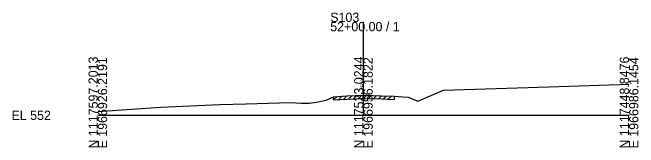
# Model space of a CAD drawing. Extents: x -26 to 163, y -10 to 24018.
# Drawn here: x -25.7 to 162.8, y 1490.3 to 1531 of the extents above; entities that cross this region are included whole.
import ezdxf

# ---------------------------------------------------------------- set-up
doc = ezdxf.new("R2010")
doc.units = 0
for name, color, linetype in [('RD_GPK_XS_Cell', 7, 'Continuous'), ('RD_XS_ExGround', 7, 'Continuous'), ('RD_XS_ExPaveRet', 7, 'Continuous'), ('RD_XS_TX_Elev_EX', 7, 'Continuous')]:
    doc.layers.add(name, color=color, linetype=linetype)

msp = doc.modelspace()

# ---------------------------------------------------------------- linework, layer by layer
at = {"layer": 'RD_GPK_XS_Cell'}
for p, q in [((80, 1500), (80, 1528.11)), ((0, 1500), (80, 1500)), ((80, 1500), (160, 1500))]:
    msp.add_line(p, q, dxfattribs=at)
at = {"layer": 'RD_XS_ExGround'}
msp.add_lwpolyline([(0, 1501.19), (18.93, 1502.4), (36.78, 1503.22), (44.69, 1503.45), (57.92, 1503.85), (61.31, 1503.69), (63.67, 1503.61), (65.87, 1504), (68.79, 1504.51), (70.06, 1505.19), (70.99, 1505.61), (75.14, 1505.83), (80, 1506.07), (80.44, 1506.09), (85.43, 1505.91), (89.23, 1505.78), (91.9, 1505.56), (93.5, 1505.43), (94.7, 1504.97), (96.41, 1504.28), (99.19, 1505.49), (104.1, 1507.61), (135.79, 1508.61), (160, 1509.37)], dxfattribs=at)
at = {"layer": 'RD_XS_ExPaveRet'}
for p, q in [((70.99, 1504.61), (72.04, 1505.66)), ((70.99, 1504.61), (70.99, 1505.61)), ((70.99, 1504.61), (75.14, 1504.83)), ((72.49, 1504.69), (73.54, 1505.74)), ((73.99, 1504.77), (75.04, 1505.82)), ((75.14, 1504.83), (80, 1505.07)), ((75.49, 1504.84), (76.54, 1505.9)), ((76.99, 1504.92), (78.04, 1505.97)), ((78.49, 1504.99), (79.54, 1506.05)), ((79.99, 1505.07), (80.99, 1506.07)), ((80, 1505.07), (80.44, 1505.09)), ((80.44, 1505.09), (85.43, 1504.91)), ((81.49, 1505.05), (82.45, 1506.02)), ((82.99, 1505), (83.95, 1505.96)), ((84.49, 1504.94), (85.45, 1505.91)), ((85.43, 1504.91), (89.23, 1504.78)), ((85.99, 1504.89), (86.95, 1505.86)), ((87.49, 1504.84), (88.45, 1505.8)), ((89.23, 1505.78), (89.23, 1504.78))]:
    msp.add_line(p, q, dxfattribs=at)

# ---------------------------------------------------------------- texts
at = {"layer": 'RD_GPK_XS_Cell'}
for s, p in [('S103', (70, 1528.11)), ('52+00.00 / 1', (70, 1525.31)), ('EL 552', (-26, 1498.6))]:
    msp.add_text(s, height=2.8, dxfattribs=at).set_placement(p)
for s, p in [('N 1117597.2013', (0, 1490)), ('E 1966926.2191', (2.8, 1490)), ('N 1117523.0244', (80, 1490)), ('E 1966956.1822', (82.8, 1490)), ('N 1117448.8476', (160, 1490)), ('E 1966986.1454', (162.8, 1490))]:
    msp.add_text(s, height=2.8, rotation=90, dxfattribs=at).set_placement(p)
at = {"layer": 'RD_XS_TX_Elev_EX'}
msp.add_text('558.07', height=0.8, rotation=90, dxfattribs=at).set_placement((79.9, 1508.07))

doc.saveas('drawing.dxf')
